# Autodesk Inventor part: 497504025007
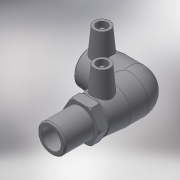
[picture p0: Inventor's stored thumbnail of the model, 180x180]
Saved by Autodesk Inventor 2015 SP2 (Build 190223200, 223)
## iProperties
Created: 2017-06
Part Number: 497504025007
Material: Generic
Description: PE Male Transition Elbow 90° 25x 3_4
Document SubType Name: Modeling
Designer: KIM
Mass: 79.3017 g
Surface Area: 281.87 cm^2
Volume: 79.3017 cm^3
Density: 1 g/cm^3
Appearance: Default
Author: KIM
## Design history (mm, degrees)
derived "497504.ipt"
feature "Solid1::497504.ipt"
feature "Solid2::497504.ipt"
tag "TaggingFeature1"
body "Solid1"
body "Solid2"
other parameters: "d2" = 36, "d5" = 32.4, "d8" = 168 deg, "d10" = 14.8, "d11" = 4.93333, "d29" = 38, "d30" = 15, "d31" = 31.2, "d34" = 5 deg, "d41" = 4, "d42" = 14, "d43" = 0, "d48" = 42, "d49" = 25, "d50" = 2.5, "d51" = 14.8, "d52" = 37, "d54" = 90 deg, "d86" = 3, "d87" = 0, "d93" = 0.1, "d94" = 9.25, "d95" = 26.441, "d96" = 18.5087, "d97" = 18, "d98" = 37, "d99" = 36, "d100" = 33.3, "d102" = 1.25, "d106" = 0, "d108" = 25.9, "d114" = 37, "d115" = 0, "d116" = -37, "d_" = 25, "L_" = 97, "L_1" = 37, "D_" = 18, "A_" = 38, "d_2" = 12, "L_2" = 37, "D_1" = 36, "R_" = 26.441
